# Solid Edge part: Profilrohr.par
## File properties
Username: bmolnar
Dokumentum tartalom típus: 0
Author: bmolnar
Last saved by: bmolnar
Revision: 81
Sűrűség: 0,000 kg/m^3
Pontosság: 0,990
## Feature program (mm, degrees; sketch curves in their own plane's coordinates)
base feature "unnamed BaseFeature 1"
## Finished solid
Body 1: solid body, 95 faces, 278 edges, 184 vertices.
  Faces by surface: plane 48, cylinder 47
  Edges by curve: line 184, circle 94
Bounding box of the edges (mm): 65.500 x 65.500 x 41.000, from (-32.75, -32.75, 0) to (32.75, 32.75, 41).
Cylindrical faces by radius (mm): R0.15 x20, R0.25 x20, R6.5 x2, R8 x4, R25 x1
Planar faces by outward normal: +x 11, +y 12, +z 1, -x 11, -y 12, -z 1
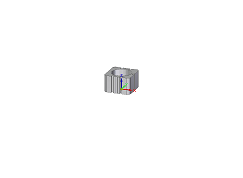
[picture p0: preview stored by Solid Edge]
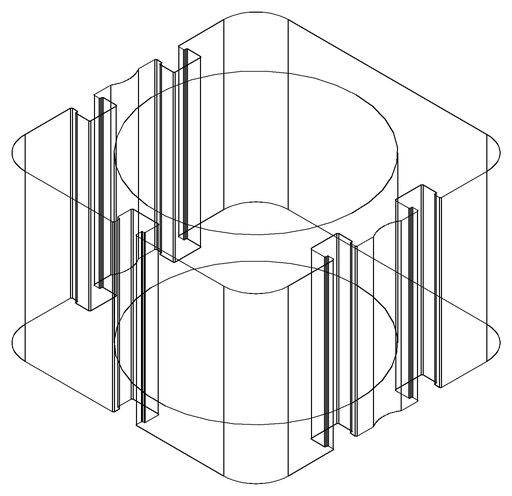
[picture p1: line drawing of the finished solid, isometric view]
